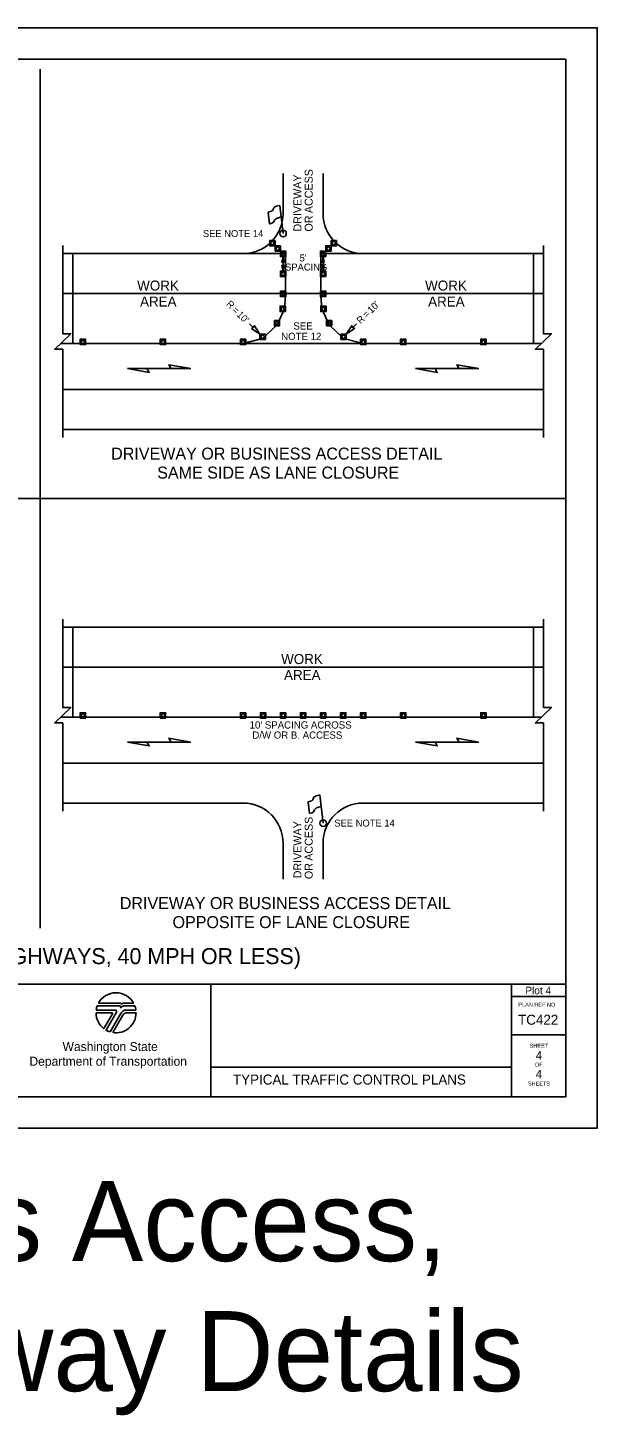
# Model space of a CAD drawing. Extents: x 99999.1 to 100095.7, y 99995 to 100010.7.
# Drawn here: x 100070.38 to 100076.06, y 99996.82 to 100010.69 of the extents above; entities that cross this region are included whole.
import ezdxf

# ---------------------------------------------------------------- set-up
doc = ezdxf.new("R2010")
doc.units = 0
for name, color, linetype in [('RD_ED_DrivewayEdge', 7, 'Continuous'), ('RD_ED_ShoulderPavedEdge', 7, 'Continuous'), ('RD_MK_LineEdgeWhite', 7, 'Continuous'), ('RD_MK_LineSkipCenter', 7, 'Continuous'), ('SH_DE_DetailHeading1Text', 7, 'Continuous'), ('SH_DE_DetailHeading2Text', 7, 'Continuous'), ('SH_GI_PlotLimits', 7, 'Continuous'), ('SH_GI_SheetBorder', 7, 'Continuous'), ('SH_GI_SheetLocationText', 7, 'Continuous'), ('SH_GI_SheetTextInCells', 7, 'Continuous'), ('SH_GI_TitleBlockText', 7, 'Continuous'), ('SH_GI_WSDOTLogo', 7, 'Continuous'), ('TR_WZ_FlaggingStation', 7, 'Continuous'), ('TR_WZ_TrafficCone', 7, 'Continuous'), ('TR_WZ_WorkAreaLabel', 7, 'Continuous'), ('TR_WZ_WorkZoneDetails', 7, 'Continuous'), ('TR_WZ_WorkZoneTextCurrent', 7, 'Continuous')]:
    doc.layers.add(name, color=color, linetype=linetype)

msp = doc.modelspace()

# ---------------------------------------------------------------- linework, layer by layer
at = {"layer": 'RD_ED_DrivewayEdge'}
for p, q in [((100072.925, 100008.83), (100072.925, 100009.23)), ((100073.325, 100008.83), (100073.325, 100009.23)), ((100072.925, 100002.536), (100072.925, 100002.176)), ((100073.325, 100002.536), (100073.325, 100002.176))]:
    msp.add_line(p, q, dxfattribs=at)
for centre, start, end in [((100072.525, 100008.83), 270, 0), ((100073.725, 100008.83), 180, 270), ((100072.525, 100002.536), 0, 90), ((100073.725, 100002.536), 90, 180)]:
    msp.add_arc(centre, 0.4, start, end, dxfattribs=at)
at = {"layer": 'RD_ED_ShoulderPavedEdge'}
for p, q in [((100070.725, 100008.43), (100072.525, 100008.43)), ((100073.725, 100008.43), (100075.525, 100008.43)), ((100070.725, 100006.67), (100075.525, 100006.67)), ((100070.725, 100004.696), (100075.525, 100004.696)), ((100070.725, 100002.936), (100072.525, 100002.936)), ((100073.725, 100002.936), (100075.525, 100002.936))]:
    msp.add_line(p, q, dxfattribs=at)
at = {"layer": 'RD_MK_LineEdgeWhite'}
for p, q in [((100070.725, 100008.03), (100075.525, 100008.03)), ((100070.725, 100007.07), (100075.525, 100007.07)), ((100070.725, 100004.296), (100075.525, 100004.296)), ((100070.725, 100003.336), (100075.525, 100003.336))]:
    msp.add_line(p, q, dxfattribs=at)
at = {"layer": 'RD_MK_LineSkipCenter'}
for points in [[(100075.504, 100007.53), (100070.704, 100007.53)], [(100075.504, 100003.796), (100070.704, 100003.796)]]:
    msp.add_lwpolyline(points, dxfattribs=at)
at = {"layer": 'SH_GI_PlotLimits'}
msp.add_lwpolyline([(100059.062, 99999.687), (100076.062, 99999.687), (100076.062, 100010.687), (100059.062, 100010.687)], close=True, dxfattribs=at)
at = {"layer": 'SH_GI_SheetBorder'}
for p, q in [((100060, 100010.375), (100075.75, 100010.375)), ((100075.75, 100010.375), (100075.75, 100000)), ((100060, 100001.126), (100075.75, 100001.126)), ((100072.205, 100001.126), (100072.205, 100000)), ((100075.208, 100001.126), (100075.208, 100000)), ((100075.208, 100001.001), (100075.75, 100001.001)), ((100075.208, 100000.618), (100075.75, 100000.618)), ((100072.205, 100000.295), (100075.208, 100000.295)), ((100060, 100000), (100075.75, 100000))]:
    msp.add_line(p, q, dxfattribs=at)
at = {"layer": 'SH_GI_WSDOTLogo'}
for p, q in [((100071.059, 100000.866), (100071.25, 100000.866)), ((100071.289, 100000.909), (100071.07, 100000.909)), ((100071.303, 100000.935), (100071.081, 100000.935)), ((100071.433, 100000.935), (100071.335, 100000.935)), ((100071.445, 100000.909), (100071.343, 100000.909)), ((100071.343, 100000.909), (100071.343, 100000.909)), ((100071.356, 100000.866), (100071.456, 100000.866)), ((100071.057, 100000.84), (100071.215, 100000.84)), ((100071.222, 100000.828), (100071.136, 100000.681)), ((100071.261, 100000.846), (100071.157, 100000.667)), ((100071.199, 100000.649), (100071.309, 100000.839)), ((100071.224, 100000.643), (100071.324, 100000.816)), ((100071.365, 100000.839), (100071.457, 100000.839))]:
    msp.add_line(p, q, dxfattribs=at)
for centre, radius, start, end in [((100071.257, 100000.84), 0.2, 28.4787, 151.532), ((100071.257, 100000.84), 0.2, 159.696, 172.5057), ((100071.25, 100000.853), 0.0131, 329.7683, 90), ((100071.289, 100000.895), 0.0148, 327.8418, 89.9985), ((100071.343, 100000.861), 0.0484, 89.9953, 147.8238), ((100071.303, 100000.926), 0.00903, 329.8742, 90.0033), ((100071.356, 100000.812), 0.0542, 90, 149.9974), ((100071.335, 100000.907), 0.0287, 90.0072, 148.1676), ((100071.257, 100000.84), 0.2, 7.4943, 20.2941), ((100071.257, 100000.84), 0.2, 179.9986, 232.8433), ((100071.215, 100000.832), 0.0082, 329.7436, 90), ((100071.257, 100000.84), 0.2, 260.5455, 359.8086), ((100071.365, 100000.792), 0.0476, 90, 150.0543), ((100071.257, 100000.84), 0.2, 239.7929, 253.0448)]:
    msp.add_arc(centre, radius, start, end, dxfattribs=at)
at = {"layer": 'TR_WZ_FlaggingStation'}
for p, q in [((100072.906, 100008.797), (100072.893, 100008.912)), ((100072.925, 100008.63), (100072.893, 100008.911)), ((100072.775, 100008.844), (100072.788, 100008.727)), ((100072.906, 100008.797), (100072.906, 100008.797)), ((100073.175, 100002.949), (100073.188, 100002.832)), ((100073.325, 100002.736), (100073.293, 100003.017)), ((100073.306, 100002.903), (100073.293, 100003.017)), ((100073.306, 100002.903), (100073.306, 100002.903))]:
    msp.add_line(p, q, dxfattribs=at)
for points in [[(100072.893, 100008.912), (100072.887, 100008.91), (100072.869, 100008.907), (100072.856, 100008.903), (100072.846, 100008.897), (100072.837, 100008.892), (100072.832, 100008.885), (100072.827, 100008.877), (100072.827, 100008.871), (100072.821, 100008.862), (100072.811, 100008.854), (100072.798, 100008.849), (100072.775, 100008.844)], [(100072.788, 100008.727), (100072.796, 100008.728), (100072.814, 100008.733), (100072.83, 100008.743), (100072.836, 100008.754), (100072.84, 100008.764), (100072.849, 100008.775), (100072.86, 100008.781), (100072.878, 100008.788), (100072.906, 100008.797)], [(100073.293, 100003.017), (100073.287, 100003.016), (100073.269, 100003.012), (100073.256, 100003.008), (100073.246, 100003.002), (100073.237, 100002.997), (100073.232, 100002.991), (100073.227, 100002.983), (100073.227, 100002.977), (100073.221, 100002.967), (100073.211, 100002.96), (100073.198, 100002.955), (100073.175, 100002.949)], [(100073.188, 100002.832), (100073.196, 100002.834), (100073.214, 100002.838), (100073.23, 100002.849), (100073.236, 100002.859), (100073.24, 100002.87), (100073.249, 100002.88), (100073.26, 100002.887), (100073.278, 100002.894), (100073.306, 100002.903)]]:
    msp.add_lwpolyline(points, dxfattribs=at)
for centre in [(100072.925, 100008.63), (100073.325, 100002.736)]:
    msp.add_circle(centre, 0.0325, dxfattribs=at)
at = {"layer": 'TR_WZ_TrafficCone'}
for points in [[(100072.845, 100008.56), (100072.845, 100008.507), (100072.792, 100008.507), (100072.792, 100008.56), (100072.845, 100008.56)], [(100072.792, 100008.56), (100072.792, 100008.507), (100072.845, 100008.507), (100072.845, 100008.56), (100072.792, 100008.56)], [(100072.898, 100008.507), (100072.898, 100008.454), (100072.845, 100008.454), (100072.845, 100008.507), (100072.898, 100008.507)], [(100072.845, 100008.507), (100072.845, 100008.454), (100072.898, 100008.454), (100072.898, 100008.507), (100072.845, 100008.507)], [(100073.352, 100008.507), (100073.352, 100008.454), (100073.405, 100008.454), (100073.405, 100008.507), (100073.352, 100008.507)], [(100073.405, 100008.507), (100073.405, 100008.454), (100073.352, 100008.454), (100073.352, 100008.507), (100073.405, 100008.507)], [(100073.405, 100008.56), (100073.405, 100008.507), (100073.458, 100008.507), (100073.458, 100008.56), (100073.405, 100008.56)], [(100073.458, 100008.56), (100073.458, 100008.507), (100073.405, 100008.507), (100073.405, 100008.56), (100073.458, 100008.56)], [(100072.898, 100008.454), (100072.952, 100008.454), (100072.952, 100008.4), (100072.898, 100008.4), (100072.898, 100008.454)], [(100072.898, 100008.4), (100072.952, 100008.4), (100072.952, 100008.454), (100072.898, 100008.454), (100072.898, 100008.4)], [(100073.352, 100008.454), (100073.298, 100008.454), (100073.298, 100008.4), (100073.352, 100008.4), (100073.352, 100008.454)], [(100073.352, 100008.4), (100073.298, 100008.4), (100073.298, 100008.454), (100073.352, 100008.454), (100073.352, 100008.4)], [(100072.898, 100008.254), (100072.952, 100008.254), (100072.952, 100008.2), (100072.898, 100008.2), (100072.898, 100008.254)], [(100072.898, 100008.2), (100072.952, 100008.2), (100072.952, 100008.254), (100072.898, 100008.254), (100072.898, 100008.2)], [(100073.352, 100008.254), (100073.298, 100008.254), (100073.298, 100008.2), (100073.352, 100008.2), (100073.352, 100008.254)], [(100073.352, 100008.2), (100073.298, 100008.2), (100073.298, 100008.254), (100073.352, 100008.254), (100073.352, 100008.2)], [(100072.898, 100008.054), (100072.952, 100008.054), (100072.952, 100008), (100072.898, 100008), (100072.898, 100008.054)], [(100072.898, 100008), (100072.952, 100008), (100072.952, 100008.054), (100072.898, 100008.054), (100072.898, 100008)], [(100073.352, 100008.054), (100073.298, 100008.054), (100073.298, 100008), (100073.352, 100008), (100073.352, 100008.054)], [(100073.352, 100008), (100073.298, 100008), (100073.298, 100008.054), (100073.352, 100008.054), (100073.352, 100008)], [(100072.896, 100007.904), (100072.949, 100007.904), (100072.949, 100007.85), (100072.896, 100007.85), (100072.896, 100007.904)], [(100072.896, 100007.85), (100072.949, 100007.85), (100072.949, 100007.904), (100072.896, 100007.904), (100072.896, 100007.85)], [(100073.354, 100007.904), (100073.301, 100007.904), (100073.301, 100007.85), (100073.354, 100007.85), (100073.354, 100007.904)], [(100073.354, 100007.85), (100073.301, 100007.85), (100073.301, 100007.904), (100073.354, 100007.904), (100073.354, 100007.85)], [(100072.838, 100007.762), (100072.891, 100007.762), (100072.891, 100007.708), (100072.838, 100007.708), (100072.838, 100007.762)], [(100072.838, 100007.708), (100072.891, 100007.708), (100072.891, 100007.762), (100072.838, 100007.762), (100072.838, 100007.708)], [(100073.412, 100007.762), (100073.359, 100007.762), (100073.359, 100007.708), (100073.412, 100007.708), (100073.412, 100007.762)], [(100073.412, 100007.708), (100073.359, 100007.708), (100073.359, 100007.762), (100073.412, 100007.762), (100073.412, 100007.708)], [(100070.899, 100007.574), (100070.952, 100007.574), (100070.952, 100007.52), (100070.899, 100007.52), (100070.899, 100007.574)], [(100070.899, 100007.52), (100070.952, 100007.52), (100070.952, 100007.574), (100070.899, 100007.574), (100070.899, 100007.52)], [(100071.699, 100007.574), (100071.752, 100007.574), (100071.752, 100007.52), (100071.699, 100007.52), (100071.699, 100007.574)], [(100071.699, 100007.52), (100071.752, 100007.52), (100071.752, 100007.574), (100071.699, 100007.574), (100071.699, 100007.52)], [(100072.499, 100007.574), (100072.552, 100007.574), (100072.552, 100007.52), (100072.499, 100007.52), (100072.499, 100007.574)], [(100072.499, 100007.52), (100072.552, 100007.52), (100072.552, 100007.574), (100072.499, 100007.574), (100072.499, 100007.52)], [(100072.694, 100007.625), (100072.748, 100007.625), (100072.748, 100007.571), (100072.694, 100007.571), (100072.694, 100007.625)], [(100072.694, 100007.571), (100072.748, 100007.571), (100072.748, 100007.625), (100072.694, 100007.625), (100072.694, 100007.571)], [(100073.556, 100007.625), (100073.502, 100007.625), (100073.502, 100007.571), (100073.556, 100007.571), (100073.556, 100007.625)], [(100073.556, 100007.571), (100073.502, 100007.571), (100073.502, 100007.625), (100073.556, 100007.625), (100073.556, 100007.571)], [(100073.699, 100007.574), (100073.752, 100007.574), (100073.752, 100007.52), (100073.699, 100007.52), (100073.699, 100007.574)], [(100073.699, 100007.52), (100073.752, 100007.52), (100073.752, 100007.574), (100073.699, 100007.574), (100073.699, 100007.52)], [(100074.099, 100007.574), (100074.152, 100007.574), (100074.152, 100007.52), (100074.099, 100007.52), (100074.099, 100007.574)], [(100074.099, 100007.52), (100074.152, 100007.52), (100074.152, 100007.574), (100074.099, 100007.574), (100074.099, 100007.52)], [(100074.899, 100007.574), (100074.952, 100007.574), (100074.952, 100007.52), (100074.899, 100007.52), (100074.899, 100007.574)], [(100074.899, 100007.52), (100074.952, 100007.52), (100074.952, 100007.574), (100074.899, 100007.574), (100074.899, 100007.52)], [(100070.899, 100003.839), (100070.952, 100003.839), (100070.952, 100003.786), (100070.899, 100003.786), (100070.899, 100003.839)], [(100070.899, 100003.786), (100070.952, 100003.786), (100070.952, 100003.839), (100070.899, 100003.839), (100070.899, 100003.786)], [(100071.699, 100003.839), (100071.752, 100003.839), (100071.752, 100003.786), (100071.699, 100003.786), (100071.699, 100003.839)], [(100071.699, 100003.786), (100071.752, 100003.786), (100071.752, 100003.839), (100071.699, 100003.839), (100071.699, 100003.786)], [(100072.499, 100003.839), (100072.552, 100003.839), (100072.552, 100003.786), (100072.499, 100003.786), (100072.499, 100003.839)], [(100072.499, 100003.786), (100072.552, 100003.786), (100072.552, 100003.839), (100072.499, 100003.839), (100072.499, 100003.786)], [(100072.699, 100003.839), (100072.752, 100003.839), (100072.752, 100003.786), (100072.699, 100003.786), (100072.699, 100003.839)], [(100072.699, 100003.786), (100072.752, 100003.786), (100072.752, 100003.839), (100072.699, 100003.839), (100072.699, 100003.786)], [(100072.899, 100003.839), (100072.952, 100003.839), (100072.952, 100003.786), (100072.899, 100003.786), (100072.899, 100003.839)], [(100072.899, 100003.786), (100072.952, 100003.786), (100072.952, 100003.839), (100072.899, 100003.839), (100072.899, 100003.786)], [(100073.099, 100003.839), (100073.152, 100003.839), (100073.152, 100003.786), (100073.099, 100003.786), (100073.099, 100003.839)], [(100073.099, 100003.786), (100073.152, 100003.786), (100073.152, 100003.839), (100073.099, 100003.839), (100073.099, 100003.786)], [(100073.299, 100003.839), (100073.352, 100003.839), (100073.352, 100003.786), (100073.299, 100003.786), (100073.299, 100003.839)], [(100073.299, 100003.786), (100073.352, 100003.786), (100073.352, 100003.839), (100073.299, 100003.839), (100073.299, 100003.786)], [(100073.499, 100003.839), (100073.552, 100003.839), (100073.552, 100003.786), (100073.499, 100003.786), (100073.499, 100003.839)], [(100073.499, 100003.786), (100073.552, 100003.786), (100073.552, 100003.839), (100073.499, 100003.839), (100073.499, 100003.786)], [(100073.699, 100003.839), (100073.752, 100003.839), (100073.752, 100003.786), (100073.699, 100003.786), (100073.699, 100003.839)], [(100073.699, 100003.786), (100073.752, 100003.786), (100073.752, 100003.839), (100073.699, 100003.839), (100073.699, 100003.786)], [(100074.099, 100003.839), (100074.152, 100003.839), (100074.152, 100003.786), (100074.099, 100003.786), (100074.099, 100003.839)], [(100074.099, 100003.786), (100074.152, 100003.786), (100074.152, 100003.839), (100074.099, 100003.839), (100074.099, 100003.786)], [(100074.899, 100003.839), (100074.952, 100003.839), (100074.952, 100003.786), (100074.899, 100003.786), (100074.899, 100003.839)], [(100074.899, 100003.786), (100074.952, 100003.786), (100074.952, 100003.839), (100074.899, 100003.839), (100074.899, 100003.786)]]:
    msp.add_lwpolyline(points, dxfattribs=at)
for centre in [(100072.818, 100008.534), (100072.872, 100008.48), (100073.378, 100008.48), (100073.432, 100008.534), (100072.925, 100008.427), (100073.325, 100008.427), (100072.925, 100008.227), (100073.325, 100008.227), (100072.925, 100008.027), (100073.325, 100008.027), (100072.922, 100007.877), (100073.328, 100007.877), (100072.865, 100007.735), (100073.385, 100007.735), (100070.926, 100007.547), (100071.726, 100007.547), (100072.526, 100007.547), (100072.721, 100007.598), (100073.529, 100007.598), (100073.726, 100007.547), (100074.126, 100007.547), (100074.926, 100007.547), (100070.926, 100003.813), (100071.726, 100003.813), (100072.526, 100003.813), (100072.726, 100003.813), (100072.926, 100003.813), (100073.126, 100003.813), (100073.326, 100003.813), (100073.526, 100003.813), (100073.726, 100003.813), (100074.126, 100003.813), (100074.926, 100003.813)]:
    msp.add_circle(centre, 0.0167, dxfattribs=at)
at = {"layer": 'TR_WZ_WorkZoneDetails'}
for p, q in [((100070.5, 100010.275), (100070.5, 100001.686)), ((100072.925, 100008.346), (100072.925, 100008.308)), ((100073.325, 100008.346), (100073.325, 100008.308)), ((100072.628, 100007.691), (100072.59, 100007.729)), ((100073.622, 100007.691), (100073.66, 100007.729)), ((100071.566, 100007.28), (100071.808, 100007.28)), ((100071.808, 100007.28), (100071.566, 100007.28)), ((100074.443, 100007.28), (100074.684, 100007.28)), ((100074.684, 100007.28), (100074.443, 100007.28)), ((100070.5, 100005.98), (100065.25, 100005.98)), ((100075.75, 100005.98), (100070.5, 100005.98)), ((100071.566, 100003.546), (100071.808, 100003.546)), ((100071.808, 100003.546), (100071.566, 100003.546)), ((100074.443, 100003.546), (100074.684, 100003.546)), ((100074.684, 100003.546), (100074.443, 100003.546))]:
    msp.add_line(p, q, dxfattribs=at)
for points in [[(100070.725, 100006.59), (100070.725, 100007.473), (100070.645, 100007.473), (100070.805, 100007.628), (100070.725, 100007.628), (100070.725, 100008.51)], [(100075.525, 100006.59), (100075.525, 100007.473), (100075.445, 100007.473), (100075.605, 100007.628), (100075.525, 100007.628), (100075.525, 100008.51)], [(100070.725, 100002.856), (100070.725, 100003.738), (100070.645, 100003.738), (100070.805, 100003.893), (100070.725, 100003.893), (100070.725, 100004.776)], [(100075.525, 100002.856), (100075.525, 100003.738), (100075.445, 100003.738), (100075.605, 100003.893), (100075.525, 100003.893), (100075.525, 100004.776)]]:
    msp.add_lwpolyline(points, dxfattribs=at)
for points in [[(100072.948, 100008.43), (100072.948, 100008.207), (100072.948, 100008.007), (100072.939, 100007.877), (100072.939, 100007.877), (100072.939, 100007.877), (100072.865, 100007.718), (100072.865, 100007.718), (100072.865, 100007.718), (100072.721, 100007.581), (100072.526, 100007.53), (100071.529, 100007.53), (100070.949, 100007.53), (100070.825, 100007.53), (100070.825, 100008.43)], [(100072.925, 100008.4), (100072.936, 100008.343), (100072.925, 100008.346), (100072.914, 100008.343)], [(100075.425, 100008.43), (100075.425, 100008.03), (100075.425, 100007.53), (100074.501, 100007.53), (100074.501, 100007.53), (100074.501, 100007.53), (100073.726, 100007.53), (100073.726, 100007.53), (100073.726, 100007.53), (100073.529, 100007.581), (100073.385, 100007.718), (100073.311, 100007.877), (100073.302, 100008.007), (100073.302, 100008.207), (100073.302, 100008.43)], [(100073.325, 100008.4), (100073.336, 100008.343), (100073.325, 100008.346), (100073.314, 100008.343)], [(100072.925, 100008.254), (100072.936, 100008.311), (100072.925, 100008.308), (100072.914, 100008.311)], [(100073.325, 100008.254), (100073.336, 100008.311), (100073.325, 100008.308), (100073.314, 100008.311)], [(100072.694, 100007.625), (100072.611, 100007.681), (100072.628, 100007.691), (100072.639, 100007.708)], [(100073.556, 100007.625), (100073.639, 100007.681), (100073.622, 100007.691), (100073.611, 100007.708)], [(100071.37, 100007.28), (100071.589, 100007.242), (100071.566, 100007.28)], [(100072.004, 100007.28), (100071.785, 100007.319), (100071.808, 100007.28)], [(100074.247, 100007.28), (100074.465, 100007.242), (100074.443, 100007.28)], [(100074.881, 100007.28), (100074.662, 100007.319), (100074.684, 100007.28)], [(100070.825, 100004.696), (100070.825, 100003.796), (100075.425, 100003.796), (100075.425, 100004.696)], [(100071.37, 100003.546), (100071.589, 100003.507), (100071.566, 100003.546)], [(100072.004, 100003.546), (100071.785, 100003.584), (100071.808, 100003.546)], [(100074.247, 100003.546), (100074.465, 100003.507), (100074.443, 100003.546)], [(100074.881, 100003.546), (100074.662, 100003.584), (100074.684, 100003.546)]]:
    msp.add_lwpolyline(points, close=True, dxfattribs=at)

# ---------------------------------------------------------------- texts
at = {"layer": 'SH_DE_DetailHeading1Text'}
msp.add_text('ALTERNATING 1-LANE, 2-WAY TRAFFIC: FLAGGER-CONTROLLED (HIGH VOLUME HIGHWAYS, 40 MPH OR LESS)', height=0.16, rotation=360, dxfattribs=at).set_placement((100061.56, 100001.326))
at = {"layer": 'SH_DE_DetailHeading2Text'}
for s, p in [('DRIVEWAY OR BUSINESS ACCESS DETAIL', (100071.208, 100006.37)), ('SAME SIDE AS LANE CLOSURE', (100071.668, 100006.18)), ('DRIVEWAY OR BUSINESS ACCESS DETAIL', (100071.294, 100001.876)), ('OPPOSITE OF LANE CLOSURE', (100071.821, 100001.686))]:
    msp.add_text(s, height=0.12, rotation=360, dxfattribs=at).set_placement(p)
at = {"layer": 'SH_GI_SheetBorder'}
msp.add_text('PLAN REF NO', height=0.04003, dxfattribs=at).set_placement((100075.275, 100000.901))
at = {"layer": 'SH_GI_SheetLocationText'}
for s, height, p in [('Plot 4', 0.075, (100075.345, 100001.025)), ('Driveway, Business Access,', 0.8, (100061.184, 99998.357)), ('or Intersecting Roadway Details', 0.8, (100060.225, 99997.057))]:
    msp.add_text(s, height=height, dxfattribs=at).set_placement(p)
at = {"layer": 'SH_GI_SheetTextInCells'}
for s, height, p in [('Washington State', 0.09007, (100070.723, 100000.457)), ('SHEET', 0.04, (100075.388, 100000.49)), ('Department of Transportation', 0.09007, (100070.392, 100000.31)), ('OF', 0.04, (100075.441, 100000.301)), ('SHEETS', 0.04, (100075.37, 100000.112))]:
    msp.add_text(s, height=height, dxfattribs=at).set_placement(p)
at = {"layer": 'SH_GI_TitleBlockText'}
for s, height, p in [('TC422', 0.1, (100075.272, 100000.72)), ('4', 0.085, (100075.449, 100000.372)), ('TYPICAL TRAFFIC CONTROL PLANS', 0.1, (100072.425, 100000.122)), ('4', 0.085, (100075.449, 100000.184))]:
    msp.add_text(s, height=height, dxfattribs=at).set_placement(p)
at = {"layer": 'TR_WZ_WorkAreaLabel'}
for s, p in [('WORK', (100071.468, 100008.06)), ('WORK', (100074.344, 100008.06)), ('AREA', (100071.497, 100007.9)), ('AREA', (100074.374, 100007.9)), ('WORK', (100072.906, 100004.326)), ('AREA', (100072.935, 100004.166))]:
    msp.add_text(s, height=0.1, dxfattribs=at).set_placement(p)
at = {"layer": 'TR_WZ_WorkZoneTextCurrent'}
for s, height, rotation, p in [('DRIVEWAY', 0.08, 90, (100073.109, 100008.65)), ('ACCESS', 0.08, 90, (100073.221, 100008.834)), ('OR', 0.08, 90, (100073.221, 100008.65)), ('R', 0.07, 315, (100072.351, 100007.919)), ("10'", 0.07, 45, (100073.808, 100007.827)), ('=', 0.07, 315, (100072.41, 100007.859)), ("10'", 0.07, 315, (100072.457, 100007.813)), ('R', 0.07, 45, (100073.701, 100007.721)), ('=', 0.07, 45, (100073.761, 100007.78)), ('ACCESS', 0.08, 90, (100073.221, 100002.36)), ('DRIVEWAY', 0.08, 90, (100073.109, 100002.184)), ('OR', 0.08, 90, (100073.221, 100002.176))]:
    msp.add_text(s, height=height, rotation=rotation, dxfattribs=at).set_placement(p)
for s, height, p in [('SEE NOTE 14', 0.07, (100072.124, 100008.595)), ("5'", 0.07, (100073.09, 100008.351)), ('SPACING', 0.07, (100072.945, 100008.26)), ('SEE', 0.072, (100073.028, 100007.67)), ('NOTE 12', 0.072, (100072.906, 100007.566)), ("10' SPACING ACROSS", 0.072, (100072.591, 100003.681)), ('D/W OR B. ACCESS', 0.072, (100072.618, 100003.58)), ('SEE NOTE 14', 0.07, (100073.437, 100002.701))]:
    msp.add_text(s, height=height, dxfattribs=at).set_placement(p)

doc.saveas('drawing.dxf')
